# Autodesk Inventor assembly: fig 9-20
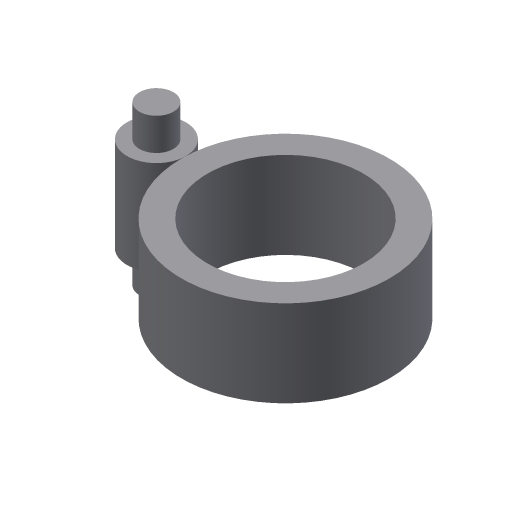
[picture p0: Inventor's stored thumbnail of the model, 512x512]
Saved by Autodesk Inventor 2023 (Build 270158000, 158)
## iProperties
Created: 2002-01
Part Number: fig 9-20
Document SubType Name: Assembly
Designer: ***
Control State: 0
Master: False
Checked Out: False
Shininess: 64.0
Length Units: 11269
Angle Units: 11279
Time Units: 11290
Mass Units: 11283
Length Display Precision: 3
Angle Display Precision: 2
Density: 0.0
Volumn: 0.0
Area: 0.0
PropertySet Name: Model Information
Author: ***
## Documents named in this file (3)
- D:\PROJECTS\Project 2022\Autodesk Inventor For Professional 2023\RESOURCES INVENTOR 2023\RESOURCES INVENTOR 2023\Inventor_2023_Part\Inventor_2023_Part\c09_Inv_2023_prt\fig 9-20.iam
- D:\PROJECTS\Project 2022\Autodesk Inventor For Professional 2023\RESOURCES INVENTOR 2023\RESOURCES INVENTOR 2023\Inventor_2023_Part\Inventor_2023_Part\c09_Inv_2023_prt\Part8.ipt
- D:\PROJECTS\Project 2022\Autodesk Inventor For Professional 2023\RESOURCES INVENTOR 2023\RESOURCES INVENTOR 2023\Inventor_2023_Part\Inventor_2023_Part\c09_Inv_2023_prt\Part9.ipt
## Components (2 placed, 2 different names)
1. Part8:1 — Flush:1
2. Part9:1 — Flush:1
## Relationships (1: Flush 1)
- Flush:1: Part8:1 ↔ Part9:1
